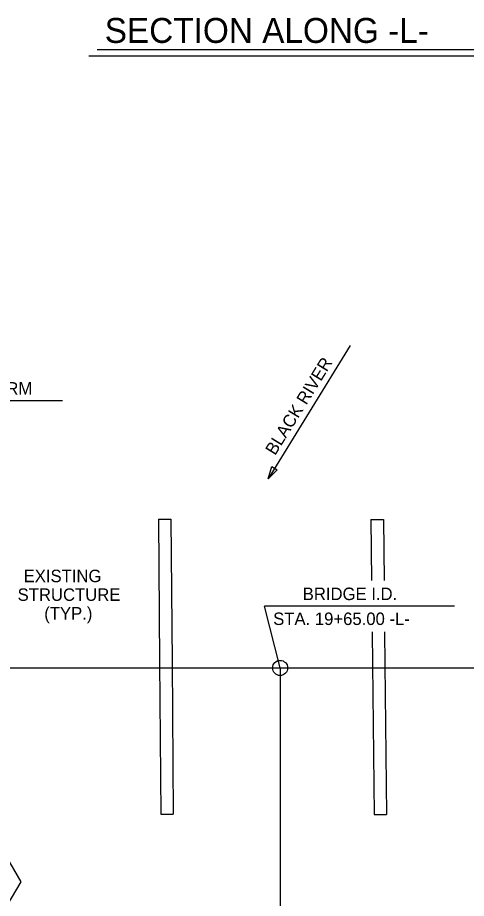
# Model space of a CAD drawing. Extents: x 471 to 2034, y -623 to 126.
# Drawn here: x 1566 to 1602, y -51.7 to 19 of the extents above; entities that cross this region are included whole.
import ezdxf

# ---------------------------------------------------------------- set-up
doc = ezdxf.new("R2010")
doc.units = 0
for name, color, linetype in [('Arrowhead Terminators CELL', 7, 'Continuous'), ('Dimension Lines', 7, 'Continuous'), ('Exist Hydro Stream or Body of Water', 7, 'Continuous'), ('Exist Structure Major Bridge Seam', 7, 'Continuous'), ('Mis -L- Lines', 7, 'Continuous'), ('Text', 7, 'Continuous'), ('Title Text', 7, 'Continuous')]:
    doc.layers.add(name, color=color, linetype=linetype)

msp = doc.modelspace()

# ---------------------------------------------------------------- linework, layer by layer
at = {"layer": 'Arrowhead Terminators CELL'}
msp.add_lwpolyline([(1586.11, -18.04), (1586.422, -17.057), (1586.848, -17.32)], close=True, dxfattribs=at)
at = {"layer": 'Dimension Lines'}
for p, q in [((1592.712, -7.338), (1586.11, -18.04)), ((1569.626, -11.78), (1549.707, -11.78)), ((1601.08, -28.271), (1585.829, -28.271)), ((1587.077, -33.216), (1585.829, -28.271)), ((1587.077, -33.216), (1587.077, -61.953))]:
    msp.add_line(p, q, dxfattribs=at)
msp.add_circle((1587.077, -33.216), 0.606, dxfattribs=at)
at = {"layer": 'Exist Hydro Stream or Body of Water'}
msp.add_lwpolyline([(1562.835, -56.21), (1566.305, -50.384), (1560.807, -40.909)], dxfattribs=at)
at = {"layer": 'Exist Structure Major Bridge Seam'}
for p, q in [((1577.32, -21.281), (1578.32, -21.281)), ((1594.365, -21.314), (1595.365, -21.314)), ((1577.513, -44.943), (1578.513, -44.943)), ((1594.623, -44.978), (1595.623, -44.978))]:
    msp.add_line(p, q, dxfattribs=at)
for points in [[(1577.32, -21.281), (1577.413, -32.755), (1577.513, -44.943)], [(1578.32, -21.281), (1578.413, -32.755), (1578.513, -44.943)], [(1594.365, -21.314), (1594.418, -26.188)], [(1595.365, -21.314), (1595.418, -26.211)], [(1594.463, -30.317), (1594.491, -32.933), (1594.623, -44.978)], [(1595.463, -30.306), (1595.491, -32.933), (1595.623, -44.978)]]:
    msp.add_lwpolyline(points, dxfattribs=at)
at = {"layer": 'Mis -L- Lines'}
msp.add_line((1529.284, -33.216), (1656.541, -33.216), dxfattribs=at)
at = {"layer": 'Title Text'}
for p, q in [((1572.411, 16.407), (1604.992, 16.407)), ((1571.729, 15.907), (1605.767, 15.907))]:
    msp.add_line(p, q, dxfattribs=at)

# ---------------------------------------------------------------- texts
at = {"layer": 'Dimension Lines'}
msp.add_text('BLACK RIVER', height=1, rotation=58.32787, dxfattribs=at).set_placement((1586.679, -16.216))
for s, p in [('EXISTING', (1566.508, -26.333)), ('STRUCTURE', (1566.024, -27.833)), ('BRIDGE I.D.', (1588.896, -27.771)), ('(TYP.)', (1568.161, -29.333)), ('STA. 19+65.00 -L-', (1586.523, -29.771))]:
    msp.add_text(s, height=1, dxfattribs=at).set_placement(p)
at = {"layer": 'Text'}
msp.add_text('1\'-0" MIN. EARTH BERM', height=1, dxfattribs=at).set_placement((1552.206, -11.28))
at = {"layer": 'Title Text'}
msp.add_text('SECTION ALONG -L-', height=2, dxfattribs=at).set_placement((1573.01, 16.944))

doc.saveas('drawing.dxf')
